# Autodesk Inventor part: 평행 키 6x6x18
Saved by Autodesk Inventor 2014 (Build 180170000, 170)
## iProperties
Created: 2026-10
Part Number: 평행 키 6x6x18
Material: 일반
Document SubType Name: Modeling
Designer: dg
Density: 1 g/cm^3
Appearance: 기본값
Author: dg
Author: jhkim
Description: 키 및 해당 키홈
Creation Date: 2026-09-29
Sending System: Autodesk Inventor 2027
Preprocessor: ST-DEVELOPER v20.1
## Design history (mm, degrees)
node "평행 키 6x6x181"
body "Solid1"
node "기준1"
